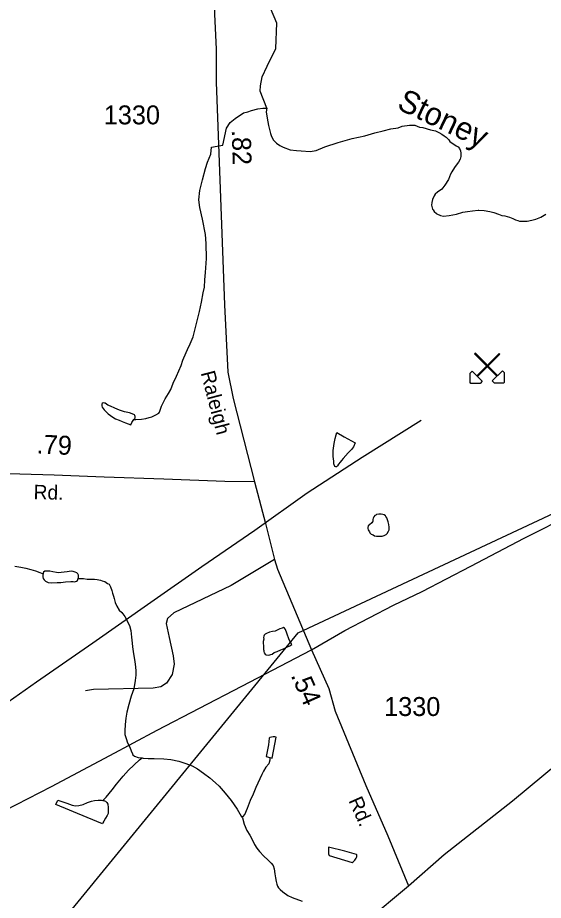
# Model space of a CAD drawing. Extents: x 2082433 to 2279600, y 546599 to 755198.
# Drawn here: x 2146372 to 2149847, y 605870 to 611701 of the extents above; entities that cross this region are included whole.
import ezdxf

# ---------------------------------------------------------------- set-up
doc = ezdxf.new("R2010")
doc.units = 0
for name, color, linetype in [('Exist Boundary Political Fire Districts', 7, 'Continuous'), ('Exist Geographical Pit Clay CELL', 7, 'Continuous'), ('Exist Hydrographic Creek Single Shore', 7, 'Continuous'), ('Exist Hydrographic Creek Single Shore Label', 7, 'Continuous'), ('Exist Hydrographic Misc Water Feature', 7, 'Continuous'), ('Exist Railroad Mainline', 7, 'Continuous'), ('Exist Road Non-System Type 51', 7, 'Continuous'), ('Exist Road Primary US Attributed', 7, 'Continuous'), ('Exist Road Secondary Mileage Hundredths English Label', 7, 'Continuous'), ('Exist Road Secondary Type 51 Attributed', 7, 'Continuous'), ('Exist Road Secondary Type 51 Label', 7, 'Continuous'), ('Exist Road Secondary Type 51 Number Label', 7, 'Continuous'), ('Exist Utilities Electrical Transmission Line', 7, 'Continuous')]:
    doc.layers.add(name, color=color, linetype=linetype)

msp = doc.modelspace()

# ---------------------------------------------------------------- linework, layer by layer
at = {"layer": 'Exist Boundary Political Fire Districts'}
msp.add_lwpolyline([(2125185.8, 609236.3), (2127409.2, 608956.3), (2130289.8, 608255.9), (2136376.8, 600637.7), (2139465.5, 602656.7), (2141242.8, 603675.4), (2141795.1, 603915), (2144979.3, 603672.9), (2148226.1, 607636.4), (2150227.4, 608573.5)], dxfattribs=at)
at = {"layer": 'Exist Geographical Pit Clay CELL'}
for points in [[(2149539.9, 609332.5), (2149544.7, 609337.3), (2149397.4, 609484.6), (2149392.6, 609479.8)], [(2149411.7, 609330.1), (2149407, 609334.9), (2149554.3, 609482.2), (2149559, 609477.4)], [(2149362.1, 609290.6), (2149362.1, 609352.7), (2149375.6, 609366.2), (2149443.1, 609298.7), (2149429.6, 609285.2), (2149367.5, 609285.2)], [(2149589.5, 609293.1), (2149589.5, 609355.2), (2149576, 609368.7), (2149508.5, 609301.2), (2149522, 609287.7), (2149584.1, 609287.7)]]:
    msp.add_lwpolyline(points, close=True, dxfattribs=at)
at = {"layer": 'Exist Hydrographic Creek Single Shore'}
for points in [[(2148019.2, 611103.7), (2147974.3, 611215.3), (2147978, 611249.7), (2147988.1, 611309), (2148021.1, 611381), (2148078.2, 611496.6), (2148086.2, 611663.7), (2147960.1, 611964.8)], [(2147140.3, 609046.2), (2147154.3, 609046.5), (2147190, 609048.8), (2147220.5, 609052.7), (2147241.9, 609058.8), (2147259.9, 609065), (2147286.1, 609076.9), (2147306, 609088.9), (2147309.9, 609095.2), (2147323.5, 609135.3), (2147347.7, 609183.2), (2147369.4, 609217.2), (2147385.2, 609245.6), (2147400.8, 609285.5), (2147422.9, 609333.6), (2147436.6, 609367.6), (2147452.4, 609403.8), (2147464.3, 609437.6), (2147486.3, 609489.9), (2147493.9, 609507.8), (2147511.7, 609545.7), (2147531.8, 609592.1), (2147551.1, 609662.2), (2147575.1, 609759.9), (2147586.7, 609822.2), (2147598.4, 609882.1), (2147606.4, 609920.2), (2147610.1, 609970), (2147613.8, 610018.1), (2147621, 610110.3), (2147619.1, 610207.9), (2147614.6, 610268.2), (2147594.1, 610369.8), (2147576.3, 610445.9), (2147569.5, 610497.6), (2147577.3, 610559.8), (2147593.3, 610629.9), (2147615, 610703.7), (2147626.7, 610746.1), (2147648.1, 610798), (2147653.3, 610845.5), (2147727.4, 610858.3), (2147753.3, 610970.3), (2147777.4, 611008.4), (2147809.2, 611034.9), (2147864.8, 611071), (2147893.1, 611078.9), (2147918.9, 611087.2), (2147958.9, 611099.4), (2147993.2, 611103.5), (2148019.2, 611103.7)], [(2148019.2, 611103.7), (2148015.1, 611079.6), (2148021.3, 611037.7), (2148029.5, 610987.7), (2148043.4, 610935.8), (2148049.8, 610915.7), (2148063.7, 610891.7), (2148082.2, 610871.9), (2148104.1, 610856.1), (2148128.1, 610844.3), (2148173.8, 610828.4), (2148216.3, 610822.4), (2148246.2, 610820.8), (2148306.3, 610816.9), (2148346.1, 610823.1), (2148401.8, 610847.1), (2148489.8, 610875.5), (2148583.5, 610901.9), (2148667.4, 610920.5), (2148733.4, 610938.9), (2148787.1, 610953.1), (2148839.2, 610967.1), (2148887, 610973.6), (2148913, 610983.5), (2148962.9, 610989.8), (2148996.9, 610989.9), (2149028.9, 610978.2)], [(2149028.9, 610978.2), (2149049.2, 610974.3), (2149101.3, 610960.3), (2149133, 610952.7), (2149156.8, 610942.6), (2149174.9, 610930.5), (2149191.1, 610920.8), (2149205.2, 610911), (2149213.2, 610902.9), (2149221.2, 610892.7), (2149229, 610882.6), (2149243, 610872.8), (2149254.8, 610864.9), (2149271, 610854.8), (2149283.3, 610846.8), (2149291.6, 610837.1), (2149299.3, 610820.9), (2149301.4, 610805.1), (2149301.6, 610783.2), (2149296.1, 610767.1), (2149285.8, 610747.1), (2149277.8, 610734.9), (2149259.8, 610710.9), (2149242.3, 610682.7), (2149234.1, 610666.9), (2149220.4, 610632.5), (2149196.6, 610594.7), (2149174.9, 610568.4), (2149147, 610548.3), (2149131, 610534.1), (2149125, 610524), (2149115, 610500), (2149109.3, 610480.2), (2149107.4, 610462.2), (2149111.7, 610444.1), (2149113.8, 610436.1), (2149117.5, 610430.3), (2149125.9, 610420.1), (2149139.8, 610408.2), (2149143.7, 610404.4), (2149167.7, 610394.7), (2149187.8, 610390.4), (2149223.7, 610394.7), (2149273.5, 610403), (2149315.5, 610415.3), (2149345.5, 610421.3), (2149377.7, 610425.4), (2149415.8, 610429.7), (2149419.7, 610430)], [(2149419.7, 610430), (2149455.6, 610426.2), (2149493.7, 610420.4), (2149519.6, 610414.5), (2149549.7, 610402.6), (2149571.9, 610394.8), (2149591.7, 610391), (2149623.9, 610382.9), (2149646.1, 610373.1), (2149661.7, 610365.4), (2149677.7, 610361.4), (2149689.8, 610357.5), (2149707.8, 610355.6), (2149739.6, 610355.7), (2149769.5, 610362.1), (2149797.6, 610370), (2149829.8, 610382.1), (2149863.4, 610402.2)], [(2146354.8, 608077.3), (2146392.5, 608071.6), (2146426.6, 608063.6), (2146458.8, 608055.9), (2146490.7, 608045.8), (2146518.4, 608035.9), (2146541, 608028.1)]]:
    msp.add_lwpolyline(points, dxfattribs=at)
at = {"layer": 'Exist Hydrographic Misc Water Feature'}
for points in [[(2147140.3, 609046.2), (2147146.5, 609052.6), (2147150, 609058.5), (2147150, 609066.6), (2147145.9, 609072.5), (2147144, 609076.5), (2147130.1, 609084.2), (2147111.8, 609090.2), (2147078, 609096.2), (2147046, 609107.9), (2147013.8, 609121.7), (2146985.7, 609133.7), (2146967.5, 609141.7), (2146959.5, 609147.8), (2146951.7, 609153.8), (2146945.8, 609153.5), (2146938, 609155.5), (2146931.8, 609151.6), (2146927.7, 609147.3), (2146927.9, 609143.6), (2146927.7, 609137.6), (2146932, 609127.6), (2146943.9, 609109.6), (2146970.2, 609083.7), (2147000.5, 609061.7), (2147020.2, 609051.8), (2147042.3, 609042), (2147062.2, 609034.1), (2147086, 609024), (2147120.3, 609012.3), (2147128, 609026.6), (2147140.3, 609046.2)], [(2148530, 608932.6), (2148602, 608892.9), (2148592.5, 608866.7), (2148578.6, 608849), (2148557.1, 608826.7), (2148524.7, 608788.6), (2148513, 608774.6), (2148502.9, 608764.3), (2148493.3, 608752.4), (2148485.3, 608740.2), (2148479.1, 608734.3), (2148474.8, 608734.5), (2148469.3, 608736.2), (2148462.9, 608752.5), (2148461.3, 608770.2), (2148456.8, 608802.1), (2148458.4, 608842.4), (2148464.4, 608888.2), (2148470.1, 608920.2), (2148478.5, 608944.5), (2148481.8, 608960.1), (2148530, 608932.6)], [(2148824.6, 608351.9), (2148820.5, 608369.9), (2148816.4, 608383.9), (2148812.5, 608395.9), (2148806.6, 608406.1), (2148802.5, 608410), (2148794.5, 608415.7), (2148786.3, 608419.7), (2148774.4, 608421.9), (2148760.3, 608421.7), (2148744.3, 608419.6), (2148738.5, 608415.6), (2148732.6, 608411.6), (2148726.2, 608403.7), (2148722.3, 608395.7), (2148720.7, 608385.5), (2148720.5, 608373.7), (2148718.4, 608369.6), (2148712.7, 608363.5), (2148696.7, 608351.4), (2148688.5, 608343.3), (2148686.9, 608333.4), (2148686.6, 608327.3), (2148688.5, 608317.4), (2148697.3, 608303.4), (2148701, 608297.6), (2148709, 608289.5), (2148721.1, 608283.6), (2148730.7, 608277.7), (2148743.2, 608275.8), (2148758.8, 608275.8), (2148781, 608275.8), (2148794.9, 608279.7), (2148807, 608286), (2148815, 608294.1), (2148823, 608308), (2148826.7, 608317.9), (2148826.7, 608326), (2148826.7, 608336.2), (2148824.6, 608351.9)], [(2146541, 608028.1), (2146538.7, 608020.3), (2146539.1, 608012.1), (2146538.9, 608006.1), (2146541.2, 607996), (2146547.1, 607988.2), (2146556.8, 607978.2), (2146575, 607970.2), (2146597, 607966.5), (2146633.1, 607968.7), (2146657.2, 607970.8), (2146688.8, 607974.9), (2146723.3, 607977), (2146739.1, 607977), (2146748.9, 607975.1), (2146761, 607979), (2146769, 607983.1), (2146772.9, 607997.1)], [(2146772.9, 607997.1), (2146774.7, 608003.3), (2146774.5, 608017.1), (2146770.6, 608027), (2146764.5, 608033.2), (2146752.8, 608039), (2146738.4, 608042.8), (2146727, 608044.9), (2146698.7, 608040.7), (2146660.5, 608036.7), (2146644.9, 608034.6), (2146628.5, 608036.3), (2146604.5, 608040.3), (2146584.5, 608044.2), (2146578.9, 608044.2), (2146568.7, 608044.2), (2146552.5, 608044.2), (2146543, 608037.9), (2146540.8, 608032.1), (2146541, 608028.1)], [(2146772.9, 607997.1), (2146807.1, 607995.1), (2146831.1, 607991.5), (2146846.9, 607991.5), (2146857, 607991.6), (2146881, 607991.7), (2146897.2, 607989.6), (2146919.1, 607985.9), (2146931.2, 607980), (2146949.2, 607976), (2146967.3, 607964), (2146976.9, 607958.1), (2146987, 607942), (2146995.2, 607918), (2146999.1, 607900.4), (2147005.2, 607878.4), (2147009.7, 607864.3), (2147017.7, 607838.4), (2147027.8, 607812.5), (2147044, 607786.5), (2147061.6, 607770.5), (2147079.9, 607744.6), (2147112.5, 607684.9), (2147120.3, 607652.9), (2147124.4, 607608.9), (2147128.9, 607568.9), (2147130.7, 607544.7), (2147136.9, 607512.9), (2147141.2, 607485.1), (2147147.1, 607446.9), (2147151.4, 607411), (2147153.3, 607387.2), (2147153.5, 607357.1), (2147149.8, 607322.8), (2147140.1, 607267.1), (2147122.3, 607219.1), (2147106.5, 607164.7), (2147094.8, 607112.9), (2147086.8, 607072.8), (2147082.9, 607030.8), (2147081.3, 606990.9), (2147081.6, 606965.7)], [(2148056.1, 607646.9), (2148035.8, 607642.6), (2148018, 607632.7), (2148007.9, 607628.6), (2148002, 607622.6), (2148000.5, 607614.7), (2147996.2, 607606.4), (2147998.5, 607594.7), (2147994, 607580.8), (2147994.6, 607566.6), (2147996.4, 607554.5), (2147996.6, 607534.6), (2147996.4, 607526.5), (2147998.5, 607520.5), (2148000.5, 607514.6), (2148002.6, 607504.9), (2148008.5, 607496.7), (2148014.7, 607490.9), (2148030.7, 607488.9), (2148054.5, 607497), (2148068.4, 607507.1), (2148088.5, 607515), (2148110.7, 607525.1), (2148134.4, 607533.2), (2148156.4, 607545.3), (2148170.3, 607551.3), (2148184.3, 607559.3), (2148166.2, 607591.3), (2148151.9, 607635.2), (2148141.8, 607659.4), (2148135.5, 607667.3), (2148129.7, 607673), (2148120.3, 607667.2), (2148104.3, 607663.1), (2148074, 607649), (2148056.1, 607646.9)], [(2147081.6, 606965.7), (2147089.3, 606939), (2147099.5, 606911.1), (2147113.7, 606881), (2147123.7, 606857.1), (2147131.9, 606837.2), (2147133.8, 606831.3), (2147144, 606823.2), (2147169.9, 606813.2), (2147194.3, 606811.2)], [(2148039.5, 606813.1), (2148055.5, 606809.1), (2148080.9, 606949.2), (2148071.1, 606951.1), (2148060.8, 606951), (2148049.1, 606949.2), (2148039.1, 606945), (2148035, 606941.1), (2148029.3, 606897), (2148015.7, 606820.8), (2148039.5, 606813.1)], [(2146935.3, 606530.4), (2146941.4, 606536.3), (2146957.2, 606552.6), (2146997.2, 606600.5), (2147024.9, 606636.8), (2147068.8, 606691), (2147106.1, 606729.2), (2147177.9, 606797.4), (2147194.3, 606811.2)], [(2147194.3, 606811.2), (2147202.1, 606809.6), (2147234.1, 606807.6), (2147275.7, 606807.8), (2147337.8, 606806.1), (2147385.8, 606800.4), (2147438.3, 606788.5), (2147484, 606774.6), (2147526.1, 606759), (2147560.1, 606739.2), (2147600.1, 606711.3), (2147642.3, 606679.3), (2147680.5, 606645.6), (2147704.4, 606623.7), (2147744.8, 606577.8), (2147782.8, 606530), (2147823.4, 606472.3), (2147849.2, 606426.2), (2147855.6, 606418.4)], [(2148039.5, 606813.1), (2148039.5, 606795.3), (2148031.5, 606773), (2148011.8, 606749.2), (2147998.1, 606722.9), (2147986, 606700.8), (2147946.6, 606614.7), (2147929, 606572.7), (2147909.3, 606528.7), (2147889.2, 606476.5), (2147883.5, 606462.4), (2147873, 606438.5), (2147859.3, 606422.3), (2147855.6, 606418.4)], [(2146935.3, 606530.4), (2146941.2, 606530.3), (2146947.4, 606528.5), (2146953.1, 606524.4), (2146961.1, 606516.3), (2146967.5, 606506.4), (2146969.5, 606500.4), (2146971.4, 606488.4), (2146971.4, 606468.6), (2146970, 606444.4), (2146963.8, 606430.4), (2146954, 606412.4), (2146942.1, 606392.3), (2146935.7, 606382.3), (2146932.2, 606376.3), (2146831.5, 606417.9), (2146625.7, 606503), (2146639, 606533), (2146697.4, 606513.2), (2146715.7, 606505.6), (2146733.5, 606499.7), (2146755.3, 606493.5), (2146775.8, 606495.7), (2146805.5, 606503.8), (2146833.4, 606515.8), (2146861.1, 606526.2), (2146879.3, 606530.3), (2146904.9, 606532.1), (2146927.1, 606532.4), (2146935.3, 606530.4)], [(2147855.6, 606418.4), (2147857.6, 606414.4), (2147869.7, 606372.4), (2147887.8, 606330.8), (2147906.2, 606300.8), (2147928.2, 606259), (2147938.4, 606238.8), (2147952.2, 606214.7), (2147970.2, 606193), (2147998.5, 606161.1), (2148026.8, 606137.4), (2148048.7, 606115.4), (2148060.8, 606101.4), (2148067, 606077.4), (2148071.1, 606045.5), (2148077.4, 606019.4), (2148081.5, 605995.7), (2148085.2, 605977.7), (2148089.3, 605963.7), (2148097.3, 605953.6), (2148107.8, 605941.8), (2148125.4, 605925.8), (2148157.2, 605901.9), (2148187.6, 605890), (2148253.8, 605864.2)], [(2148534.3, 606195.7), (2148425.8, 606221), (2148426.2, 606205.2), (2148426.2, 606193), (2148426.2, 606177.2), (2148430.5, 606167.2), (2148582.5, 606119.9), (2148590.7, 606125.6), (2148600.5, 606135.8), (2148610, 606149.8), (2148614.3, 606157.6), (2148614.5, 606163.7), (2148614.3, 606169.8), (2148612.2, 606173.8), (2148534.3, 606195.7)]]:
    msp.add_lwpolyline(points, dxfattribs=at)
at = {"layer": 'Exist Railroad Mainline'}
for points in [[(2149044.8, 607910.7), (2149367, 608077.1), (2149719.9, 608262.9), (2150043.4, 608426.2), (2150421.6, 608636.8), (2150569.4, 608702), (2151152.1, 609004.5), (2151687, 609275.8), (2152608.9, 609758.4), (2152879.1, 609887.4), (2153077, 609969.7), (2153323.9, 610067.6), (2153579.7, 610165.4), (2153792.7, 610254.8)], [(2148314.2, 607525.5), (2148534.2, 607652.5), (2148857.4, 607819.9), (2149044.8, 607910.7)], [(2144236.9, 605087.5), (2144390.9, 605213.2), (2144551.7, 605340), (2144808.6, 605522.8), (2145033.7, 605687.9), (2145247, 605838.7), (2145492.3, 605995.7), (2145767.5, 606164.9), (2145980.8, 606289.8), (2146208.4, 606423.2), (2146595.1, 606622.3), (2146982.2, 606826), (2147295.4, 606993.3), (2147853.8, 607284.4), (2148314.2, 607525.5)]]:
    msp.add_lwpolyline(points, dxfattribs=at)
at = {"layer": 'Exist Road Non-System Type 51'}
msp.add_lwpolyline([(2148070.8, 608121.6), (2147783.7, 607950.8), (2147404.4, 607769.6), (2147363.4, 607732.1), (2147353.2, 607697.9), (2147373.7, 607605.6), (2147401, 607486), (2147407.8, 607431.3), (2147394.2, 607363), (2147356.6, 607304.9), (2147319, 607281), (2147267.7, 607270.7), (2146874.8, 607263.9), (2146820.1, 607253.6)], dxfattribs=at)
at = {"layer": 'Exist Road Primary US Attributed'}
for points in [[(2148954.9, 605965.8), (2149192.2, 606172.7), (2149642.3, 606527.9), (2150042.8, 606860), (2150431.7, 607183.2), (2150718.5, 607403.4), (2151092.3, 607621.8), (2151483.9, 607849.1), (2152131.2, 608213.2), (2152314.1, 608307.3)], [(2147758.5, 604764.2), (2148005.5, 605031.9), (2148126.6, 605170.8), (2148477.3, 605549.8), (2148676.3, 605733), (2148954.9, 605965.8)]]:
    msp.add_lwpolyline(points, dxfattribs=at)
at = {"layer": 'Exist Road Secondary Type 51 Attributed'}
for points in [[(2147865.2, 612611), (2147829.1, 612489.7), (2147798.8, 612364.5), (2147717.3, 612067.4), (2147689.7, 611949.5), (2147678.9, 611886.2), (2147674.9, 611816.2), (2147672.8, 611723.2), (2147683.4, 611492.5), (2147685, 611273.9), (2147694.4, 610980.9), (2147739.3, 609802.9), (2147761.5, 609358.1), (2147796, 609184.6), (2147937.2, 608635.3)], [(2147937.2, 608635.3), (2147741.8, 608637.3), (2147338.7, 608652), (2146943.5, 608664.6), (2146613.8, 608678.3), (2146157.1, 608692.3), (2145727.2, 608720.3), (2145456, 608731.7), (2145040.3, 608748.5), (2144859, 608747.5), (2144597.9, 608732.8), (2144369.9, 608705.5), (2144165.5, 608675.1), (2144027.4, 608652)], [(2147937.2, 608635.3), (2148010.6, 608359.5), (2148070.8, 608121.6), (2148089.6, 608057), (2148314.2, 607525.5)], [(2148314.2, 607525.5), (2148429.9, 607269.7), (2148470.3, 607119.9), (2148674.3, 606629.9), (2148818.8, 606296.9), (2148954.9, 605965.8)]]:
    msp.add_lwpolyline(points, dxfattribs=at)
at = {"layer": 'Exist Utilities Electrical Transmission Line'}
msp.add_lwpolyline([(2146119.5, 607050.1), (2146496.2, 607313.6), (2146868.9, 607571.2), (2147253.7, 607838.8), (2147590.5, 608076.2), (2147939.3, 608315.7), (2148286.3, 608561.2), (2148649, 608798.6), (2149039.9, 609042.3)], dxfattribs=at)

# ---------------------------------------------------------------- texts
at = {"layer": 'Exist Hydrographic Creek Single Shore Label'}
msp.add_text('Stoney', height=150, rotation=334.59048, dxfattribs=at).set_placement((2148872, 611101.4))
at = {"layer": 'Exist Road Secondary Mileage Hundredths English Label'}
for s, rotation, p in [('.82', 271.74217, (2147787.4, 610957.6)), ('.79', 357.17501, (2146495.7, 608823)), ('.54', 293.79295, (2148175.7, 607356.3))]:
    msp.add_text(s, height=125, rotation=rotation, dxfattribs=at).set_placement(p)
at = {"layer": 'Exist Road Secondary Type 51 Label'}
for s, rotation, p in [('Raleigh', 284.49176, (2147581.6, 609355.1)), ('Rd.', 358.63291, (2146476.9, 608520.5)), ('Rd.', 293.84955, (2148557.4, 606529.7))]:
    msp.add_text(s, height=95, rotation=rotation, dxfattribs=at).set_placement(p)
at = {"layer": 'Exist Road Secondary Type 51 Number Label'}
for p in [(2146941.4, 610996), (2148794.1, 607088)]:
    msp.add_text('1330', height=125, dxfattribs=at).set_placement(p)

doc.saveas('drawing.dxf')
